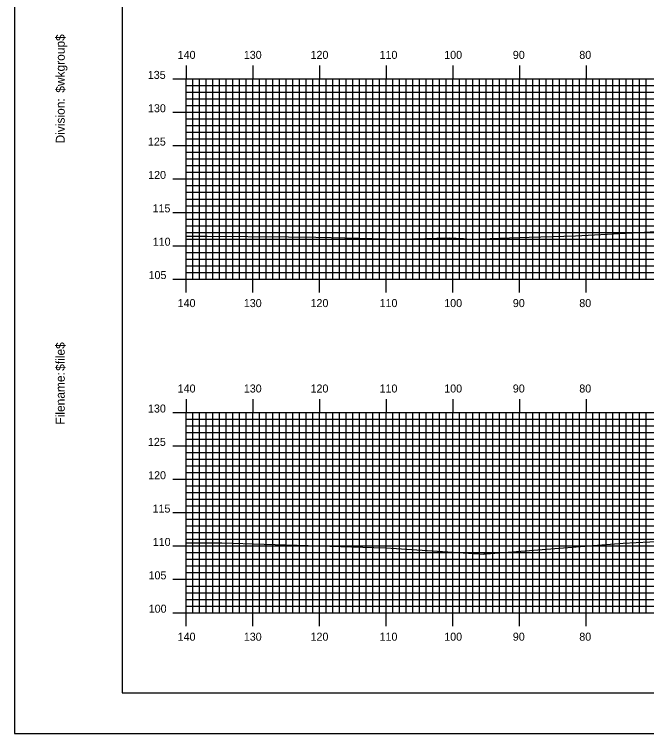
# Model space of a CAD drawing. Extents: x 1788550 to 1788893, y 442591 to 442811.
# Drawn here: x 1788549.9 to 1788644.7, y 442590.5 to 442698.3 of the extents above; entities that cross this region are included whole.
import ezdxf

# ---------------------------------------------------------------- set-up
doc = ezdxf.new("R2010")
doc.units = 0
for name, color, linetype in [('BORDER', 7, 'Continuous'), ('H_V ANNOTATION', 7, 'Continuous'), ('MAJOR', 7, 'Continuous'), ('MINOR', 7, 'Continuous'), ('PLOT BOUNDARY', 7, 'Continuous'), ('S_Roadway_Centerline', 7, 'Continuous')]:
    doc.layers.add(name, color=color, linetype=linetype)

msp = doc.modelspace()

# ---------------------------------------------------------------- linework, layer by layer
at = {"layer": 'BORDER'}
msp.add_lwpolyline([(1788566.04, 442596.67), (1788886.04, 442596.67), (1788886.04, 442806.67), (1788566.04, 442806.67)], close=True, dxfattribs=at)
at = {"layer": 'MAJOR'}
for p, q in [((1788575.64, 442690.67), (1788575.64, 442688.67)), ((1788585.64, 442690.67), (1788585.64, 442688.67)), ((1788595.64, 442690.67), (1788595.64, 442688.67)), ((1788605.64, 442690.67), (1788605.64, 442688.67)), ((1788615.64, 442690.67), (1788615.64, 442688.67)), ((1788625.64, 442690.67), (1788625.64, 442688.67)), ((1788635.64, 442690.67), (1788635.64, 442688.67)), ((1788573.64, 442688.67), (1788575.64, 442688.67)), ((1788575.64, 442688.67), (1788855.64, 442688.67)), ((1788575.64, 442658.67), (1788575.64, 442688.67)), ((1788575.64, 442658.67), (1788575.64, 442688.67)), ((1788575.64, 442688.67), (1788855.64, 442688.67)), ((1788585.64, 442658.67), (1788585.64, 442688.67)), ((1788595.64, 442658.67), (1788595.64, 442688.67)), ((1788605.64, 442658.67), (1788605.64, 442688.67)), ((1788615.64, 442658.67), (1788615.64, 442688.67)), ((1788625.64, 442658.67), (1788625.64, 442688.67)), ((1788635.64, 442658.67), (1788635.64, 442688.67)), ((1788573.64, 442683.67), (1788575.64, 442683.67)), ((1788575.64, 442683.67), (1788855.64, 442683.67)), ((1788573.64, 442678.67), (1788575.64, 442678.67)), ((1788575.64, 442678.67), (1788855.64, 442678.67)), ((1788573.64, 442673.67), (1788575.64, 442673.67)), ((1788575.64, 442673.67), (1788855.64, 442673.67)), ((1788573.64, 442668.67), (1788575.64, 442668.67)), ((1788575.64, 442668.67), (1788855.64, 442668.67)), ((1788573.64, 442663.67), (1788575.64, 442663.67)), ((1788575.64, 442663.67), (1788855.64, 442663.67)), ((1788573.64, 442658.67), (1788575.64, 442658.67)), ((1788575.64, 442658.67), (1788855.64, 442658.67)), ((1788575.64, 442658.67), (1788855.64, 442658.67)), ((1788575.64, 442656.66), (1788575.64, 442658.67)), ((1788585.64, 442656.66), (1788585.64, 442658.67)), ((1788595.64, 442656.66), (1788595.64, 442658.67)), ((1788605.64, 442656.66), (1788605.64, 442658.67)), ((1788615.64, 442656.66), (1788615.64, 442658.67)), ((1788625.64, 442656.66), (1788625.64, 442658.67)), ((1788635.64, 442656.66), (1788635.64, 442658.67)), ((1788575.64, 442640.67), (1788575.64, 442638.67)), ((1788585.64, 442640.67), (1788585.64, 442638.67)), ((1788595.64, 442640.67), (1788595.64, 442638.67)), ((1788605.64, 442640.67), (1788605.64, 442638.67)), ((1788615.64, 442640.67), (1788615.64, 442638.67)), ((1788625.64, 442640.67), (1788625.64, 442638.67)), ((1788635.64, 442640.67), (1788635.64, 442638.67)), ((1788573.64, 442638.67), (1788575.64, 442638.67)), ((1788575.64, 442638.67), (1788855.64, 442638.67)), ((1788575.64, 442608.67), (1788575.64, 442638.67)), ((1788575.64, 442608.67), (1788575.64, 442638.67)), ((1788575.64, 442638.67), (1788855.64, 442638.67)), ((1788585.64, 442608.67), (1788585.64, 442638.67)), ((1788595.64, 442608.67), (1788595.64, 442638.67)), ((1788605.64, 442608.67), (1788605.64, 442638.67)), ((1788615.64, 442608.67), (1788615.64, 442638.67)), ((1788625.64, 442608.67), (1788625.64, 442638.67)), ((1788635.64, 442608.67), (1788635.64, 442638.67)), ((1788573.64, 442633.67), (1788575.64, 442633.67)), ((1788575.64, 442633.67), (1788855.64, 442633.67)), ((1788573.64, 442628.67), (1788575.64, 442628.67)), ((1788575.64, 442628.67), (1788855.64, 442628.67)), ((1788573.64, 442623.67), (1788575.64, 442623.67)), ((1788575.64, 442623.67), (1788855.64, 442623.67)), ((1788573.64, 442618.67), (1788575.64, 442618.67)), ((1788575.64, 442618.67), (1788855.64, 442618.67)), ((1788573.64, 442613.67), (1788575.64, 442613.67)), ((1788575.64, 442613.67), (1788855.64, 442613.67)), ((1788573.64, 442608.67), (1788575.64, 442608.67)), ((1788575.64, 442608.67), (1788855.64, 442608.67)), ((1788575.64, 442608.67), (1788855.64, 442608.67)), ((1788575.64, 442606.66), (1788575.64, 442608.67)), ((1788585.64, 442606.66), (1788585.64, 442608.67)), ((1788595.64, 442606.66), (1788595.64, 442608.67)), ((1788605.64, 442606.66), (1788605.64, 442608.67)), ((1788615.64, 442606.66), (1788615.64, 442608.67)), ((1788625.64, 442606.66), (1788625.64, 442608.67)), ((1788635.64, 442606.66), (1788635.64, 442608.67))]:
    msp.add_line(p, q, dxfattribs=at)
at = {"layer": 'MINOR'}
for p, q in [((1788576.64, 442658.67), (1788576.64, 442688.67)), ((1788577.64, 442658.67), (1788577.64, 442688.67)), ((1788578.64, 442658.67), (1788578.64, 442688.67)), ((1788579.64, 442658.67), (1788579.64, 442688.67)), ((1788580.64, 442658.67), (1788580.64, 442688.67)), ((1788581.64, 442658.67), (1788581.64, 442688.67)), ((1788582.64, 442658.67), (1788582.64, 442688.67)), ((1788583.64, 442658.67), (1788583.64, 442688.67)), ((1788584.64, 442658.67), (1788584.64, 442688.67)), ((1788586.64, 442658.67), (1788586.64, 442688.67)), ((1788587.64, 442658.67), (1788587.64, 442688.67)), ((1788588.64, 442658.67), (1788588.64, 442688.67)), ((1788589.64, 442658.67), (1788589.64, 442688.67)), ((1788590.64, 442658.67), (1788590.64, 442688.67)), ((1788591.64, 442658.67), (1788591.64, 442688.67)), ((1788592.64, 442658.67), (1788592.64, 442688.67)), ((1788593.64, 442658.67), (1788593.64, 442688.67)), ((1788594.64, 442658.67), (1788594.64, 442688.67)), ((1788596.64, 442658.67), (1788596.64, 442688.67)), ((1788597.64, 442658.67), (1788597.64, 442688.67)), ((1788598.64, 442658.67), (1788598.64, 442688.67)), ((1788599.64, 442658.67), (1788599.64, 442688.67)), ((1788600.64, 442658.67), (1788600.64, 442688.67)), ((1788601.64, 442658.67), (1788601.64, 442688.67)), ((1788602.64, 442658.67), (1788602.64, 442688.67)), ((1788603.64, 442658.67), (1788603.64, 442688.67)), ((1788604.64, 442658.67), (1788604.64, 442688.67)), ((1788606.64, 442658.67), (1788606.64, 442688.67)), ((1788607.64, 442658.67), (1788607.64, 442688.67)), ((1788608.64, 442658.67), (1788608.64, 442688.67)), ((1788609.64, 442658.67), (1788609.64, 442688.67)), ((1788610.64, 442658.67), (1788610.64, 442688.67)), ((1788611.64, 442658.67), (1788611.64, 442688.67)), ((1788612.64, 442658.67), (1788612.64, 442688.67)), ((1788613.64, 442658.67), (1788613.64, 442688.67)), ((1788614.64, 442658.67), (1788614.64, 442688.67)), ((1788616.64, 442658.67), (1788616.64, 442688.67)), ((1788617.64, 442658.67), (1788617.64, 442688.67)), ((1788618.64, 442658.67), (1788618.64, 442688.67)), ((1788619.64, 442658.67), (1788619.64, 442688.67)), ((1788620.64, 442658.67), (1788620.64, 442688.67)), ((1788621.64, 442658.67), (1788621.64, 442688.67)), ((1788622.64, 442658.67), (1788622.64, 442688.67)), ((1788623.64, 442658.67), (1788623.64, 442688.67)), ((1788624.64, 442658.67), (1788624.64, 442688.67)), ((1788626.64, 442658.67), (1788626.64, 442688.67)), ((1788627.64, 442658.67), (1788627.64, 442688.67)), ((1788628.64, 442658.67), (1788628.64, 442688.67)), ((1788629.64, 442658.67), (1788629.64, 442688.67)), ((1788630.64, 442658.67), (1788630.64, 442688.67)), ((1788631.64, 442658.67), (1788631.64, 442688.67)), ((1788632.64, 442658.67), (1788632.64, 442688.67)), ((1788633.64, 442658.67), (1788633.64, 442688.67)), ((1788634.64, 442658.67), (1788634.64, 442688.67)), ((1788636.64, 442658.67), (1788636.64, 442688.67)), ((1788637.64, 442658.67), (1788637.64, 442688.67)), ((1788638.64, 442658.67), (1788638.64, 442688.67)), ((1788639.64, 442658.67), (1788639.64, 442688.67)), ((1788640.64, 442658.67), (1788640.64, 442688.67)), ((1788641.64, 442658.67), (1788641.64, 442688.67)), ((1788642.64, 442658.67), (1788642.64, 442688.67)), ((1788643.64, 442658.67), (1788643.64, 442688.67)), ((1788644.64, 442658.67), (1788644.64, 442688.67)), ((1788575.64, 442687.67), (1788855.64, 442687.67)), ((1788575.64, 442687.67), (1788577.65, 442687.67)), ((1788575.64, 442686.67), (1788855.64, 442686.67)), ((1788575.64, 442686.67), (1788577.65, 442686.67)), ((1788575.64, 442685.67), (1788855.64, 442685.67)), ((1788575.64, 442685.67), (1788577.65, 442685.67)), ((1788575.64, 442684.67), (1788855.64, 442684.67)), ((1788575.64, 442684.67), (1788577.65, 442684.67)), ((1788575.64, 442682.67), (1788855.64, 442682.67)), ((1788575.64, 442682.67), (1788577.65, 442682.67)), ((1788575.64, 442681.67), (1788855.64, 442681.67)), ((1788575.64, 442681.67), (1788577.65, 442681.67)), ((1788575.64, 442680.67), (1788855.64, 442680.67)), ((1788575.64, 442680.67), (1788577.65, 442680.67)), ((1788575.64, 442679.67), (1788855.64, 442679.67)), ((1788575.64, 442679.67), (1788577.65, 442679.67)), ((1788575.64, 442677.67), (1788855.64, 442677.67)), ((1788575.64, 442677.67), (1788577.65, 442677.67)), ((1788575.64, 442676.67), (1788855.64, 442676.67)), ((1788575.64, 442676.67), (1788577.65, 442676.67)), ((1788575.64, 442675.67), (1788855.64, 442675.67)), ((1788575.64, 442675.67), (1788577.65, 442675.67)), ((1788575.64, 442674.67), (1788855.64, 442674.67)), ((1788575.64, 442674.67), (1788577.65, 442674.67)), ((1788575.64, 442672.67), (1788855.64, 442672.67)), ((1788575.64, 442672.67), (1788577.65, 442672.67)), ((1788575.64, 442671.67), (1788855.64, 442671.67)), ((1788575.64, 442671.67), (1788577.65, 442671.67)), ((1788575.64, 442670.67), (1788855.64, 442670.67)), ((1788575.64, 442670.67), (1788577.65, 442670.67)), ((1788575.64, 442669.67), (1788855.64, 442669.67)), ((1788575.64, 442669.67), (1788577.65, 442669.67)), ((1788575.64, 442667.67), (1788855.64, 442667.67)), ((1788575.64, 442667.67), (1788577.65, 442667.67)), ((1788575.64, 442666.67), (1788855.64, 442666.67)), ((1788575.64, 442666.67), (1788577.65, 442666.67)), ((1788575.64, 442665.67), (1788855.64, 442665.67)), ((1788575.64, 442665.67), (1788577.65, 442665.67)), ((1788575.64, 442664.67), (1788855.64, 442664.67)), ((1788575.64, 442664.67), (1788577.65, 442664.67)), ((1788575.64, 442662.67), (1788855.64, 442662.67)), ((1788575.64, 442662.67), (1788577.65, 442662.67)), ((1788575.64, 442661.67), (1788855.64, 442661.67)), ((1788575.64, 442661.67), (1788577.65, 442661.67)), ((1788575.64, 442660.67), (1788855.64, 442660.67)), ((1788575.64, 442660.67), (1788577.65, 442660.67)), ((1788575.64, 442659.67), (1788855.64, 442659.67)), ((1788575.64, 442659.67), (1788577.65, 442659.67)), ((1788576.64, 442608.67), (1788576.64, 442638.67)), ((1788577.64, 442608.67), (1788577.64, 442638.67)), ((1788578.64, 442608.67), (1788578.64, 442638.67)), ((1788579.64, 442608.67), (1788579.64, 442638.67)), ((1788580.64, 442608.67), (1788580.64, 442638.67)), ((1788581.64, 442608.67), (1788581.64, 442638.67)), ((1788582.64, 442608.67), (1788582.64, 442638.67)), ((1788583.64, 442608.67), (1788583.64, 442638.67)), ((1788584.64, 442608.67), (1788584.64, 442638.67)), ((1788586.64, 442608.67), (1788586.64, 442638.67)), ((1788587.64, 442608.67), (1788587.64, 442638.67)), ((1788588.64, 442608.67), (1788588.64, 442638.67)), ((1788589.64, 442608.67), (1788589.64, 442638.67)), ((1788590.64, 442608.67), (1788590.64, 442638.67)), ((1788591.64, 442608.67), (1788591.64, 442638.67)), ((1788592.64, 442608.67), (1788592.64, 442638.67)), ((1788593.64, 442608.67), (1788593.64, 442638.67)), ((1788594.64, 442608.67), (1788594.64, 442638.67)), ((1788596.64, 442608.67), (1788596.64, 442638.67)), ((1788597.64, 442608.67), (1788597.64, 442638.67)), ((1788598.64, 442608.67), (1788598.64, 442638.67)), ((1788599.64, 442608.67), (1788599.64, 442638.67)), ((1788600.64, 442608.67), (1788600.64, 442638.67)), ((1788601.64, 442608.67), (1788601.64, 442638.67)), ((1788602.64, 442608.67), (1788602.64, 442638.67)), ((1788603.64, 442608.67), (1788603.64, 442638.67)), ((1788604.64, 442608.67), (1788604.64, 442638.67)), ((1788606.64, 442608.67), (1788606.64, 442638.67)), ((1788607.64, 442608.67), (1788607.64, 442638.67)), ((1788608.64, 442608.67), (1788608.64, 442638.67)), ((1788609.64, 442608.67), (1788609.64, 442638.67)), ((1788610.64, 442608.67), (1788610.64, 442638.67)), ((1788611.64, 442608.67), (1788611.64, 442638.67)), ((1788612.64, 442608.67), (1788612.64, 442638.67)), ((1788613.64, 442608.67), (1788613.64, 442638.67)), ((1788614.64, 442608.67), (1788614.64, 442638.67)), ((1788616.64, 442608.67), (1788616.64, 442638.67)), ((1788617.64, 442608.67), (1788617.64, 442638.67)), ((1788618.64, 442608.67), (1788618.64, 442638.67)), ((1788619.64, 442608.67), (1788619.64, 442638.67)), ((1788620.64, 442608.67), (1788620.64, 442638.67)), ((1788621.64, 442608.67), (1788621.64, 442638.67)), ((1788622.64, 442608.67), (1788622.64, 442638.67)), ((1788623.64, 442608.67), (1788623.64, 442638.67)), ((1788624.64, 442608.67), (1788624.64, 442638.67)), ((1788626.64, 442608.67), (1788626.64, 442638.67)), ((1788627.64, 442608.67), (1788627.64, 442638.67)), ((1788628.64, 442608.67), (1788628.64, 442638.67)), ((1788629.64, 442608.67), (1788629.64, 442638.67)), ((1788630.64, 442608.67), (1788630.64, 442638.67)), ((1788631.64, 442608.67), (1788631.64, 442638.67)), ((1788632.64, 442608.67), (1788632.64, 442638.67)), ((1788633.64, 442608.67), (1788633.64, 442638.67)), ((1788634.64, 442608.67), (1788634.64, 442638.67)), ((1788636.64, 442608.67), (1788636.64, 442638.67)), ((1788637.64, 442608.67), (1788637.64, 442638.67)), ((1788638.64, 442608.67), (1788638.64, 442638.67)), ((1788639.64, 442608.67), (1788639.64, 442638.67)), ((1788640.64, 442608.67), (1788640.64, 442638.67)), ((1788641.64, 442608.67), (1788641.64, 442638.67)), ((1788642.64, 442608.67), (1788642.64, 442638.67)), ((1788643.64, 442608.67), (1788643.64, 442638.67)), ((1788644.64, 442608.67), (1788644.64, 442638.67)), ((1788575.64, 442637.67), (1788855.64, 442637.67)), ((1788575.64, 442637.67), (1788577.65, 442637.67)), ((1788575.64, 442636.67), (1788855.64, 442636.67)), ((1788575.64, 442636.67), (1788577.65, 442636.67)), ((1788575.64, 442635.67), (1788855.64, 442635.67)), ((1788575.64, 442635.67), (1788577.65, 442635.67)), ((1788575.64, 442634.67), (1788855.64, 442634.67)), ((1788575.64, 442634.67), (1788577.65, 442634.67)), ((1788575.64, 442632.67), (1788855.64, 442632.67)), ((1788575.64, 442632.67), (1788577.65, 442632.67)), ((1788575.64, 442631.67), (1788855.64, 442631.67)), ((1788575.64, 442631.67), (1788577.65, 442631.67)), ((1788575.64, 442630.67), (1788855.64, 442630.67)), ((1788575.64, 442630.67), (1788577.65, 442630.67)), ((1788575.64, 442629.67), (1788855.64, 442629.67)), ((1788575.64, 442629.67), (1788577.65, 442629.67)), ((1788575.64, 442627.67), (1788855.64, 442627.67)), ((1788575.64, 442627.67), (1788577.65, 442627.67)), ((1788575.64, 442626.67), (1788855.64, 442626.67)), ((1788575.64, 442626.67), (1788577.65, 442626.67)), ((1788575.64, 442625.67), (1788855.64, 442625.67)), ((1788575.64, 442625.67), (1788577.65, 442625.67)), ((1788575.64, 442624.67), (1788855.64, 442624.67)), ((1788575.64, 442624.67), (1788577.65, 442624.67)), ((1788575.64, 442622.67), (1788855.64, 442622.67)), ((1788575.64, 442622.67), (1788577.65, 442622.67)), ((1788575.64, 442621.67), (1788855.64, 442621.67)), ((1788575.64, 442621.67), (1788577.65, 442621.67)), ((1788575.64, 442620.67), (1788855.64, 442620.67)), ((1788575.64, 442620.67), (1788577.65, 442620.67)), ((1788575.64, 442619.67), (1788855.64, 442619.67)), ((1788575.64, 442619.67), (1788577.65, 442619.67)), ((1788575.64, 442617.67), (1788855.64, 442617.67)), ((1788575.64, 442617.67), (1788577.65, 442617.67)), ((1788575.64, 442616.67), (1788855.64, 442616.67)), ((1788575.64, 442616.67), (1788577.65, 442616.67)), ((1788575.64, 442615.67), (1788855.64, 442615.67)), ((1788575.64, 442615.67), (1788577.65, 442615.67)), ((1788575.64, 442614.67), (1788855.64, 442614.67)), ((1788575.64, 442614.67), (1788577.65, 442614.67)), ((1788575.64, 442612.67), (1788855.64, 442612.67)), ((1788575.64, 442612.67), (1788577.65, 442612.67)), ((1788575.64, 442611.67), (1788855.64, 442611.67)), ((1788575.64, 442611.67), (1788577.65, 442611.67)), ((1788575.64, 442610.67), (1788855.64, 442610.67)), ((1788575.64, 442610.67), (1788577.65, 442610.67)), ((1788575.64, 442609.67), (1788855.64, 442609.67)), ((1788575.64, 442609.67), (1788577.65, 442609.67))]:
    msp.add_line(p, q, dxfattribs=at)
at = {"layer": 'PLOT BOUNDARY'}
msp.add_lwpolyline([(1788549.86, 442590.55), (1788889.86, 442590.55), (1788889.86, 442810.55), (1788549.86, 442810.55)], close=True, dxfattribs=at)
at = {"layer": 'S_Roadway_Centerline'}
for points in [[(1788575.64, 442665.09), (1788578.79, 442665.09), (1788590.95, 442665), (1788595.07, 442664.95), (1788597.36, 442664.91), (1788607.73, 442664.64), (1788615.05, 442664.84), (1788617.21, 442664.73), (1788618.26, 442664.65), (1788627.08, 442664.93), (1788634.02, 442665.14), (1788643.53, 442665.63), (1788653.56, 442666.27)], [(1788575.64, 442619.13), (1788580.99, 442619.12), (1788587.33, 442618.93), (1788603.77, 442618.45), (1788605.62, 442618.4), (1788615.63, 442617.75), (1788620.28, 442617.46), (1788620.29, 442617.47), (1788620.39, 442617.47), (1788620.64, 442617.5), (1788623.28, 442617.69), (1788641.17, 442619.11), (1788643.11, 442619.21), (1788653.38, 442619.7)]]:
    msp.add_lwpolyline(points, dxfattribs=at)

# ---------------------------------------------------------------- texts
at = {"layer": 'BORDER'}
for s, p in [('$wkgroup$', (1788557.41, 442686.6)), ('Division:', (1788557.41, 442679)), ('$file$', (1788557.41, 442644.92)), ('Filename:', (1788557.41, 442636.86))]:
    msp.add_text(s, height=1.339, rotation=90, dxfattribs=at).set_placement(p)
at = {"layer": 'H_V ANNOTATION'}
for s, p in [('140', (1788574.35, 442691.67)), ('130', (1788584.27, 442691.67)), ('120', (1788594.28, 442691.67)), ('110', (1788604.63, 442691.67)), ('100', (1788614.33, 442691.67)), ('90', (1788624.62, 442691.67)), ('80', (1788634.59, 442691.67)), ('135', (1788569.87, 442688.67)), ('130', (1788569.9, 442683.67)), ('125', (1788569.89, 442678.67)), ('120', (1788569.92, 442673.67)), ('115', (1788570.58, 442668.67)), ('110', (1788570.61, 442663.67)), ('105', (1788569.98, 442658.67)), ('140', (1788574.35, 442654.47)), ('130', (1788584.27, 442654.47)), ('120', (1788594.28, 442654.47)), ('110', (1788604.63, 442654.47)), ('100', (1788614.33, 442654.47)), ('90', (1788624.62, 442654.47)), ('80', (1788634.59, 442654.47)), ('140', (1788574.35, 442641.67)), ('130', (1788584.27, 442641.67)), ('120', (1788594.28, 442641.67)), ('110', (1788604.63, 442641.67)), ('100', (1788614.33, 442641.67)), ('90', (1788624.62, 442641.67)), ('80', (1788634.59, 442641.67)), ('130', (1788569.9, 442638.67)), ('125', (1788569.89, 442633.67)), ('120', (1788569.92, 442628.67)), ('115', (1788570.58, 442623.67)), ('110', (1788570.61, 442618.67)), ('105', (1788569.98, 442613.67)), ('100', (1788570.01, 442608.67)), ('140', (1788574.35, 442604.47)), ('130', (1788584.27, 442604.47)), ('120', (1788594.28, 442604.47)), ('110', (1788604.63, 442604.47)), ('100', (1788614.33, 442604.47)), ('90', (1788624.62, 442604.47)), ('80', (1788634.59, 442604.47))]:
    msp.add_text(s, height=1.2, dxfattribs=at).set_placement(p)
at = {"layer": 'MAJOR'}
for p in [(1788575.63, 442658.67), (1788575.63, 442608.67)]:
    msp.add_text('-', height=0.012, dxfattribs=at).set_placement(p)

doc.saveas('drawing.dxf')
